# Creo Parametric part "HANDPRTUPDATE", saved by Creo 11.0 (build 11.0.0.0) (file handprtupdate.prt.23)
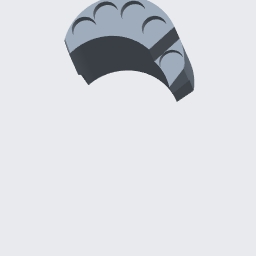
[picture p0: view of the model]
Units: Inch lbm Second (Pro/E Default); INCH, POUND, SECS
Materials in the file: LTE800_36

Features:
  1. datum plane "RIGHT"
  2. datum plane "TOP"
  3. datum plane "FRONT"
  4. coordinate system
  5. curve
  6. protrusion
  7. round
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
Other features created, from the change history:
  extruded cut "Extrude 3"
  datum plane "DTM3"
  sketch "Sketch 4"
  extruded cut "Extrude 4"
  shell "Shell 1" (3 times)
  datum plane "DTM4"
  sketch "Sketch 5"
  extruded cut "Extrude 5"
  mirror "Mirror 1"
  extruded cut "Extrude 5 (2)"
  datum plane "DTM5"
  sketch "Sketch 6"
  extruded cut "Extrude 6"
  sketch "Sketch 7"
  extrusion "Extrude 7"

Surfaces: 27 plane, 21 cylinder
